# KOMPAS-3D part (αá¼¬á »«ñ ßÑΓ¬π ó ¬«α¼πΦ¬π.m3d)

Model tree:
1. Эскиз:1
2. Операция выдавливания:1
     Расстояние 1 = 3
3. Эскиз:2
4. Вырезать элемент выдавливания:1
     Расстояние 1 = 3
5. Эскиз:3
6. Операция выдавливания:3
     Расстояние 1 = 4
